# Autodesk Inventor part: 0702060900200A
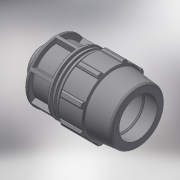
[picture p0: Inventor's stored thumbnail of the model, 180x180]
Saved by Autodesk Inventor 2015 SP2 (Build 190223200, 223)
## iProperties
Created: 2017-02
Part Number: 0702060900200A
Material: Generic
Description: PLASSON MALE ADAPTOR 90-2"
Document SubType Name: Modeling
Designer: KIM
Mass: 964.158 g
Surface Area: 1468.9 cm^2
Volume: 964.158 cm^3
Density: 1 g/cm^3
Appearance: Default
Author: KIM
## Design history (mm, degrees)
derived "87020.ipt"
feature "Solid1::87020.ipt"
tag "TaggingFeature1"
body "Solid1"
other parameters: "d4" = 32.42857, "d5" = 56.75, "d7" = 152, "d8" = 114, "d9" = 32.42857, "d11" = 6.48571, "d12" = 121.6, "d13" = 120 deg, "d14" = 117, "d15" = 6 deg, "d16" = 136.8, "d18" = 4.5, "d19" = 35 deg, "d20" = 17.5 deg, "d21" = 141.36, "d23" = 0, "d25" = 360 deg, "d27" = 3.04, "d34" = 7.6, "d36" = 0, "d42" = 68.1, "d43" = 4.56, "d46" = 2.7, "d51" = 227, "d52" = 26, "d53" = 1.8, "d55" = 360 deg, "d57" = 59.614, "d58" = 41.7298, "d59" = 45.4, "d61" = 134.064, "d62" = 3.55571, "d63" = 3.55571, "d66" = 7.11143, "E_" = 152, "H_" = 227, "l_2" = 26, "R_" = 59.614, "d60" = 17.77857
